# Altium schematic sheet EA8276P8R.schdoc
size 127 x 101 mm
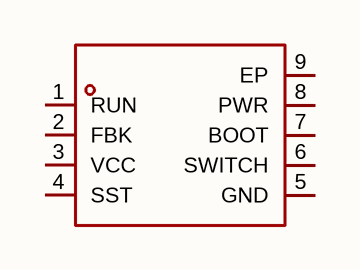
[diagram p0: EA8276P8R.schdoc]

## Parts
U?  ea8276p8r  [ESOP-8_L4.9-W3.9-P1.27-LS6.0-BL-EP-2]  (value not drawn)

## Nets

Not connected (* = marked no-connect by the designer): U? 1(RUN) 2(FBK) 3(VCC) 4(SST) 5(GND) 6(SWITCH) 7(BOOT) 8(PWR) 9(EP)

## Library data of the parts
U? = ea8276p8r: 功能类型:降压型;工作电压:4.5V~18V;输出电压:756mV~10V;输出电流:6A;输出类型:可调;; Manufacturer: everanalog(申风); AddInBom: yes; ModelId: 0078439d9e964752ad4b3f828dcb5664; ModelTransform: 192.913,236.22,0,0,0,0,0,0,0; Function: 降压型; Output Current: 6A; Frequency - Switching: 750kHz; Synchronous Rectifier: 是; Number of Outputs: 1; Topology: 降压式; Quiescent Current: 400uA; Switch tube (built-in/external): 内置; Output Type: 可调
